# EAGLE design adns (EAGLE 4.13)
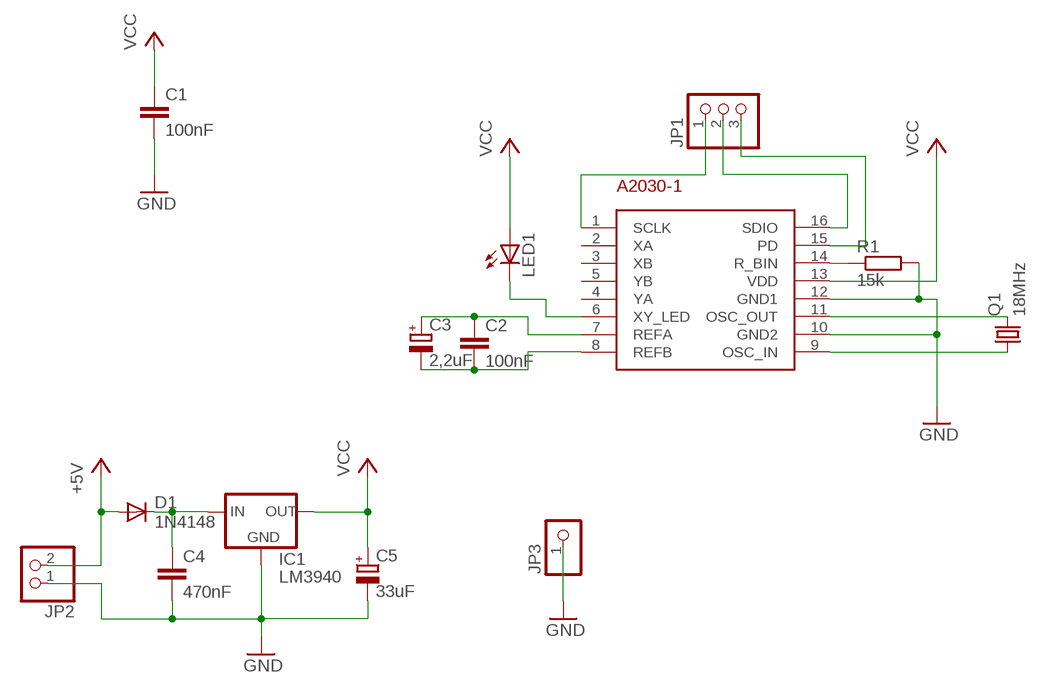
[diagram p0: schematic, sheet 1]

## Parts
A2030-1  A2030DIP  [A2030PKG]
C1  100nF  C-EU025-030X050  [C025-030X050]
C2  100nF  C-EU025-030X050  [C025-030X050]
C3  2,2uF  CPOL-EUE2.5-7  [E2,5-7]
C4  470nF  C-EU025-030X050  [C025-030X050]
C5  33uF  CPOL-EUE2.5-7  [E2,5-7]
D1  1N4148  [DO35-10]
IC1  LM3940  78XXS  [78XXS]
JP1  PINHD-1X3  [1X03]
JP2  PINHD-1X2  [1X02]
JP3  PINHD-1X1  [1X01]
LED1  LED5MM  [LED5MM]
Q1  18MHz  CRYTALHC18U-V  [HC18U-V]
R1  15k  R-EU_0204/7  [0204/7]

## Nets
+5V: D1.A JP2.2
GND: A2030-1.10(GND2) A2030-1.12(GND1) C1.2 C4.2 C5.- IC1.GND JP2.1 JP3.1 R1.2
N$1: A2030-1.11(OSC_OUT) Q1.2
N$2: A2030-1.9(OSC_IN) Q1.1
N$3: A2030-1.14(R_BIN) R1.1
N$4: A2030-1.7(REFA) C2.1 C3.+
N$5: A2030-1.8(REFB) C2.2 C3.-
N$6: A2030-1.6(XY_LED) LED1.K(C)
N$7: C4.1 D1.C IC1.IN
N$11: A2030-1.1(SCLK) JP1.1
N$12: A2030-1.16(SDIO) JP1.2
N$13: A2030-1.15(PD) JP1.3
VCC: A2030-1.13(VDD) C1.1 C5.+ IC1.OUT LED1.A
Unconnected: A2030-1.2(XA) A2030-1.3(XB) A2030-1.4(YA) A2030-1.5(YB)

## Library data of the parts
A2030-1 = agilnet:A2030: ADNS-2030 Optical Mouse Sensor from Agilent Technologies
C1 C2 C4 = rcl:C-EU: CAPACITOR, European symbol
C3 C5 = rcl:CPOL-EU: POLARIZED CAPACITOR, European symbol
D1 = diode:1N4148: DIODE
IC1 = v-reg:78XXS: VOLTAGE REGULATOR
JP1 = pinhead:PINHD-1X3: PIN HEADER
JP2 = pinhead:PINHD-1X2: PIN HEADER
JP3 = pinhead:PINHD-1X1: PIN HEADER
LED1 = led:LED: LED
Q1 = crystal:CRYTAL: CRYSTAL
R1 = rcl:R-EU_: RESISTOR, European symbol

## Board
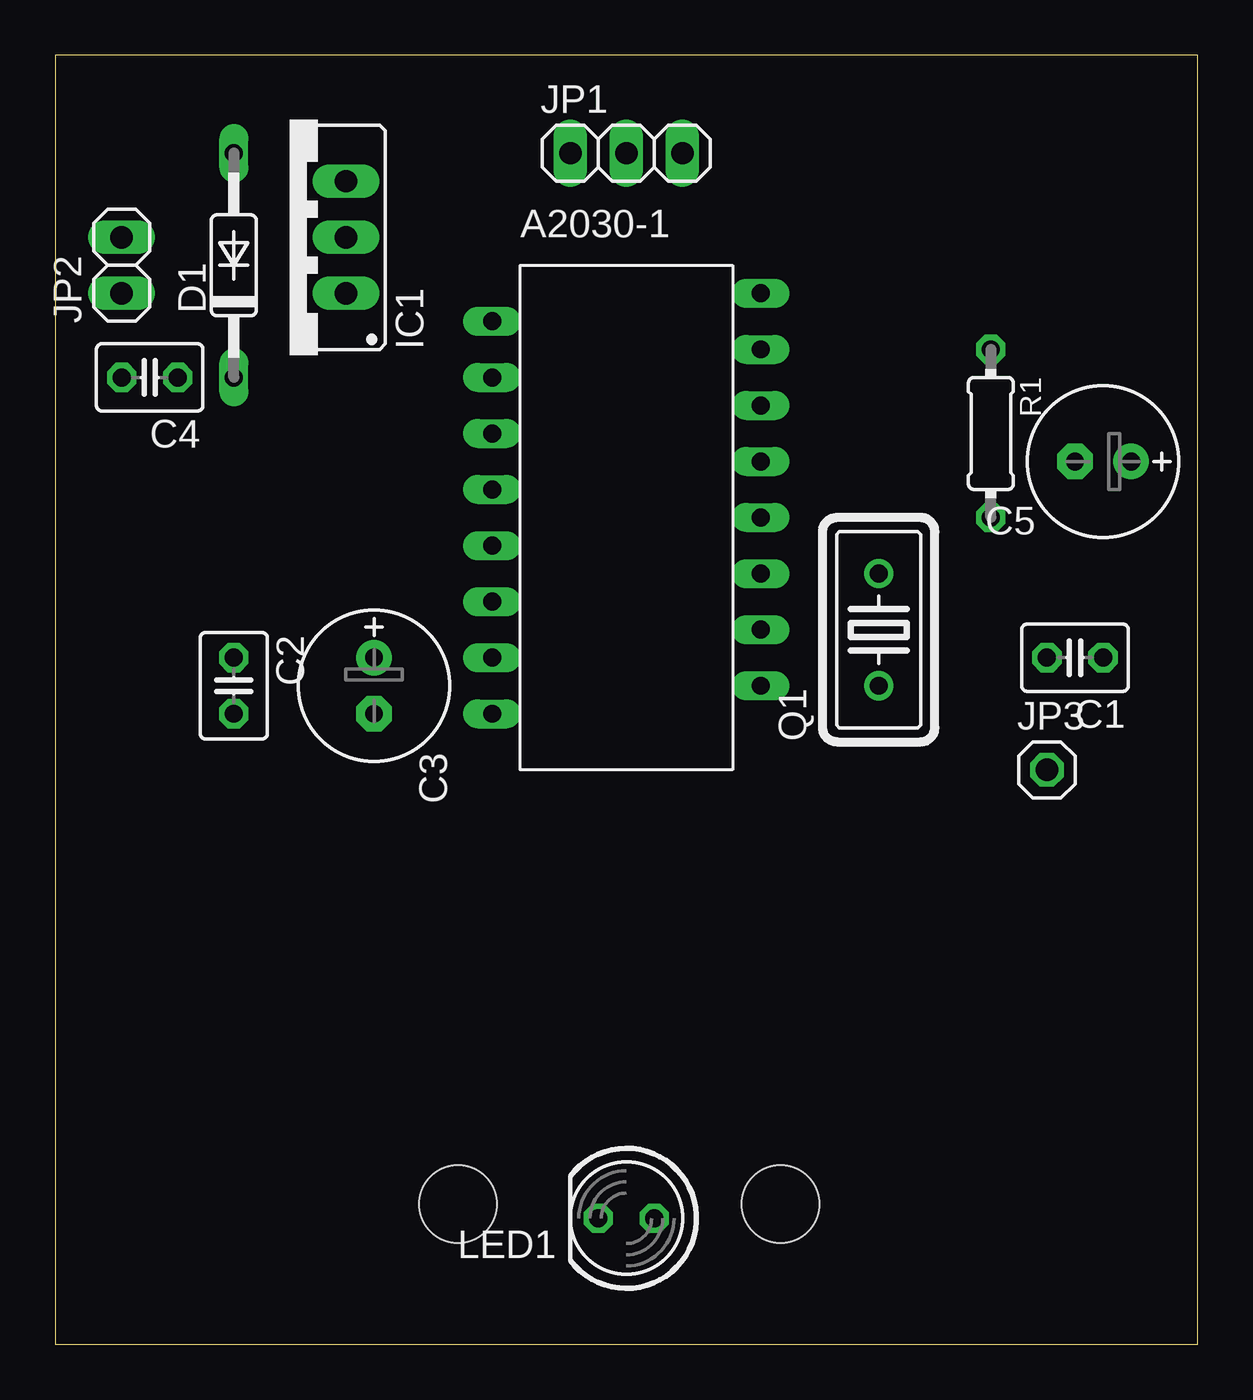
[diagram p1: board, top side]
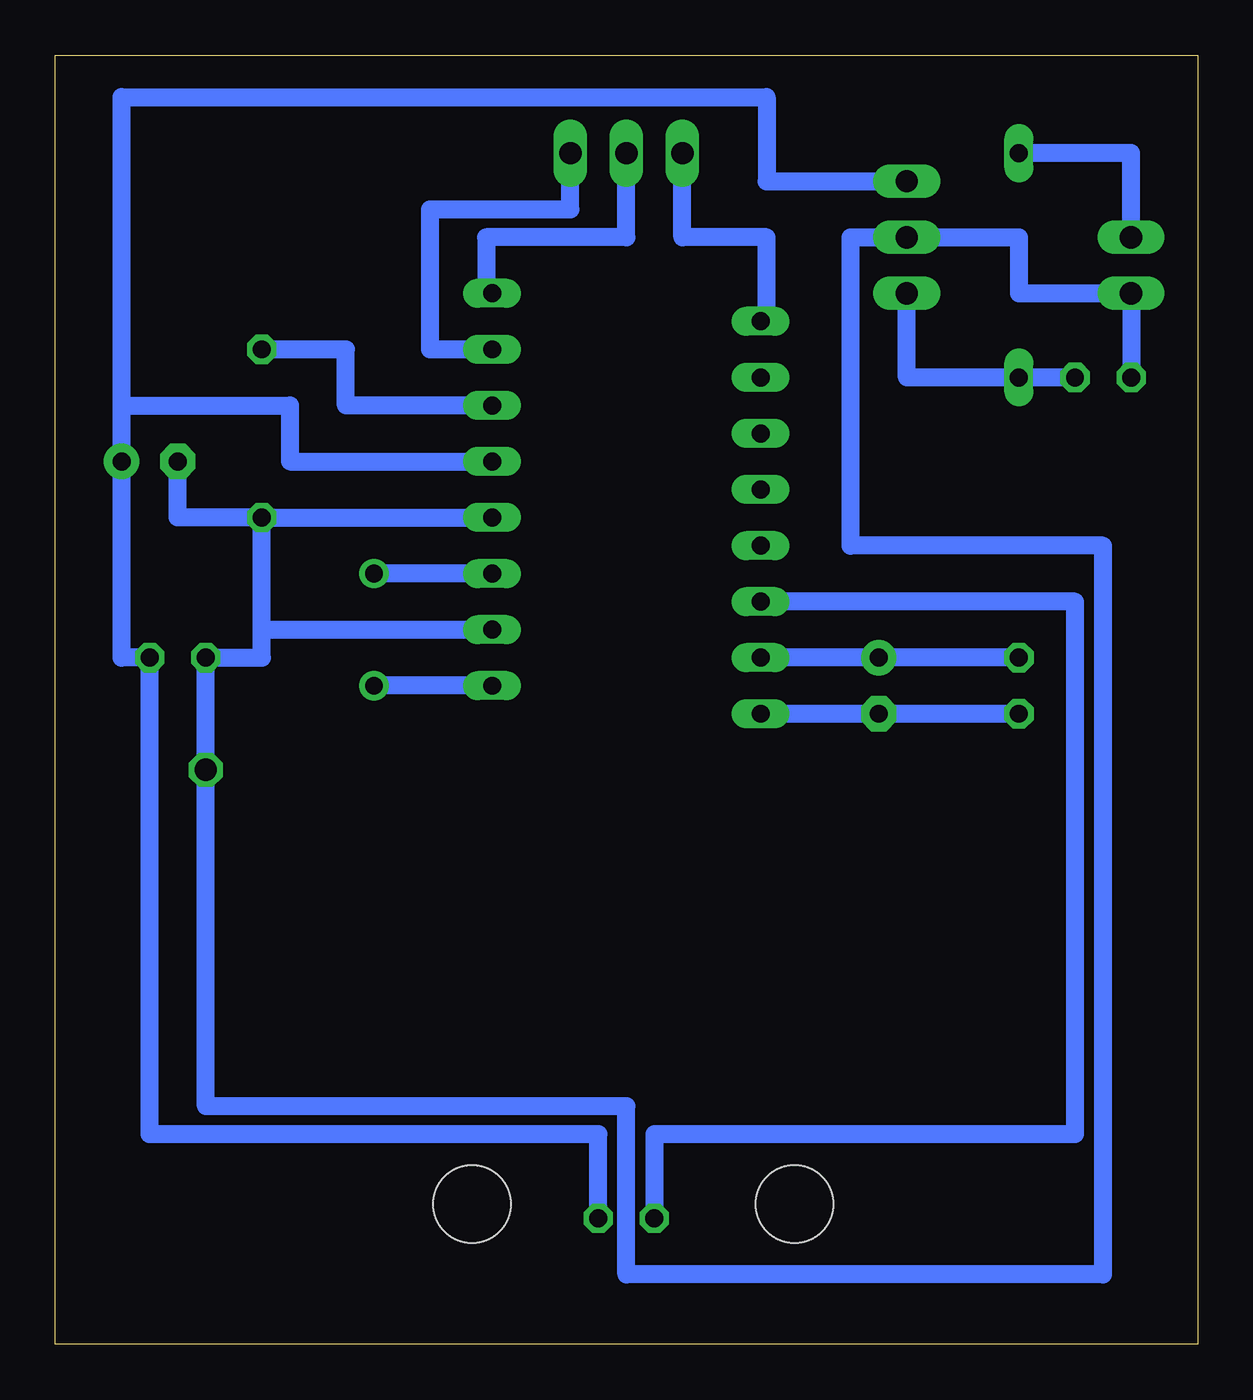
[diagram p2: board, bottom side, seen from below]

Size 51.74 x 58.41 mm. Coordinates in mm from the lower left corner, seen from the top.
Outline: 0,0 51.74,0 51.74,58.41 0,58.41 0,0
Copper layers (1*16): Top 0.035mm / dielectric 1.5mm / Bottom 0.035mm
Design rules "default": minimum track width 10mil, minimum drill 24mil, track to track 8mil, track to pad 8mil, pad to pad 8mil, via to via 8mil, smd to smd 8mil, copper to edge 40mil, drill to drill 8mil, minimum pad ring 10mil, minimum via ring 8mil, stop-mask expansion 4mil, vias tented up to drill 0mil, thermal gap 10mil
Holes 3.5 mm at 18.25,6.34 32.85,6.34

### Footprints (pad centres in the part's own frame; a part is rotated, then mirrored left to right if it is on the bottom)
A2030PKG = drill 0.813 long: 1 -6.08,10.16; 2 -6.08,7.62; 3 -6.08,5.08; 4 -6.08,2.54; 5 -6.08,0; 6 -6.08,-2.54; 7 -6.08,-5.08; 8 -6.08,-7.62; 9 6.08,-6.35; 10 6.08,-3.81; 11 6.08,-1.27; 12 6.08,1.27; 13 6.08,3.81; 14 6.08,6.35; 15 6.08,8.89; 16 6.08,11.43
C025-030X050 = drill 0.813 octagon: 1 -1.27,0; 2 1.27,0
E2,5-7 = drill 0.813 pad 1.6 round: + -1.27,0 | drill 0.813 pad 1.6 octagon: - 1.27,0
DO35-10 = drill 0.813 long: A 5.08,0; C -5.08,0
78XXS = drill 1.016 long: GND 0,-2.54; IN -2.54,-2.54; OUT 2.54,-2.54
1X03 = drill 1.016 long: 1 -2.54,0; 2 0,0; 3 2.54,0
1X02 = drill 1.016 long: 1 -1.27,0; 2 1.27,0
1X01 = drill 1.016 octagon: 1 0,0
LED5MM = drill 0.813 octagon: A -1.27,0; K 1.27,0
HC18U-V = drill 0.813 round: 1 -2.54,0; 2 2.54,0
0204/7 = drill 0.813 octagon: 1 -3.81,0; 2 3.81,0

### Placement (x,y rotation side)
A2030-1  25.87,36.19 0 top
C1  46.19,31.11 180 top
C2  8.09,29.84 270 top
C3  14.44,29.84 270 top
C4  4.28,43.81 180 top
C5  47.46,40 180 top
D1  8.09,48.89 90 top
IC1  10.63,50.16 90 top
JP1  25.87,53.97 0 top
JP2  3.01,48.89 90 top
JP3  44.92,26.03 0 top
LED1  25.87,5.71 180 top
Q1  37.3,32.38 90 top
R1  42.38,41.27 270 top

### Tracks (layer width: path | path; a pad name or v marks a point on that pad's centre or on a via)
+5V
  Bottom 0.813: JP2.2 3.01,53.97 D1.A
GND
  Bottom 0.813: C4.2 JP2.1 8.09,47.62 8.09,50.16 IC1.GND 15.71,50.16 15.71,36.19 4.28,36.19 4.28,3.17 25.87,3.17 25.87,10.79 44.92,10.79 JP3.1 C1.2 42.38,31.11 42.38,32.38 | 42.38,32.38 A2030-1.10 | R1.2 A2030-1.12 | 42.38,32.38 R1.2 | R1.2 46.19,37.46 C5.-
N$1
  Bottom 0.813: A2030-1.11 Q1.2
N$2
  Bottom 0.813: A2030-1.9 Q1.1
N$3
  Bottom 0.813: A2030-1.14 38.57,42.54 38.57,45.08 R1.1
N$4
  Bottom 0.813: C2.1 C3.+ A2030-1.7
N$5
  Bottom 0.813: A2030-1.8 C3.- C2.2
N$6
  Bottom 0.813: LED1.K 24.6,9.52 5.55,9.52 5.55,33.65 A2030-1.6
N$7
  Bottom 0.813: IC1.IN 13.17,43.81 D1.C C4.1
N$11
  Bottom 0.813: A2030-1.1 19.52,46.35 19.52,50.16 23.33,50.16 JP1.1
N$12
  Bottom 0.813: A2030-1.16 32.22,47.62 32.22,50.16 25.87,50.16 JP1.2
N$13
  Bottom 0.813: A2030-1.15 34.76,45.08 34.76,51.43 28.41,51.43 JP1.3
VCC
  Bottom 0.813: LED1.A 27.14,9.52 47.46,9.52 C1.1 48.73,31.11 C5.+ 48.73,42.54 | IC1.OUT 19.52,52.7 19.52,56.51 48.73,56.51 48.73,42.54 | 48.73,42.54 41.11,42.54 41.11,40 A2030-1.13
